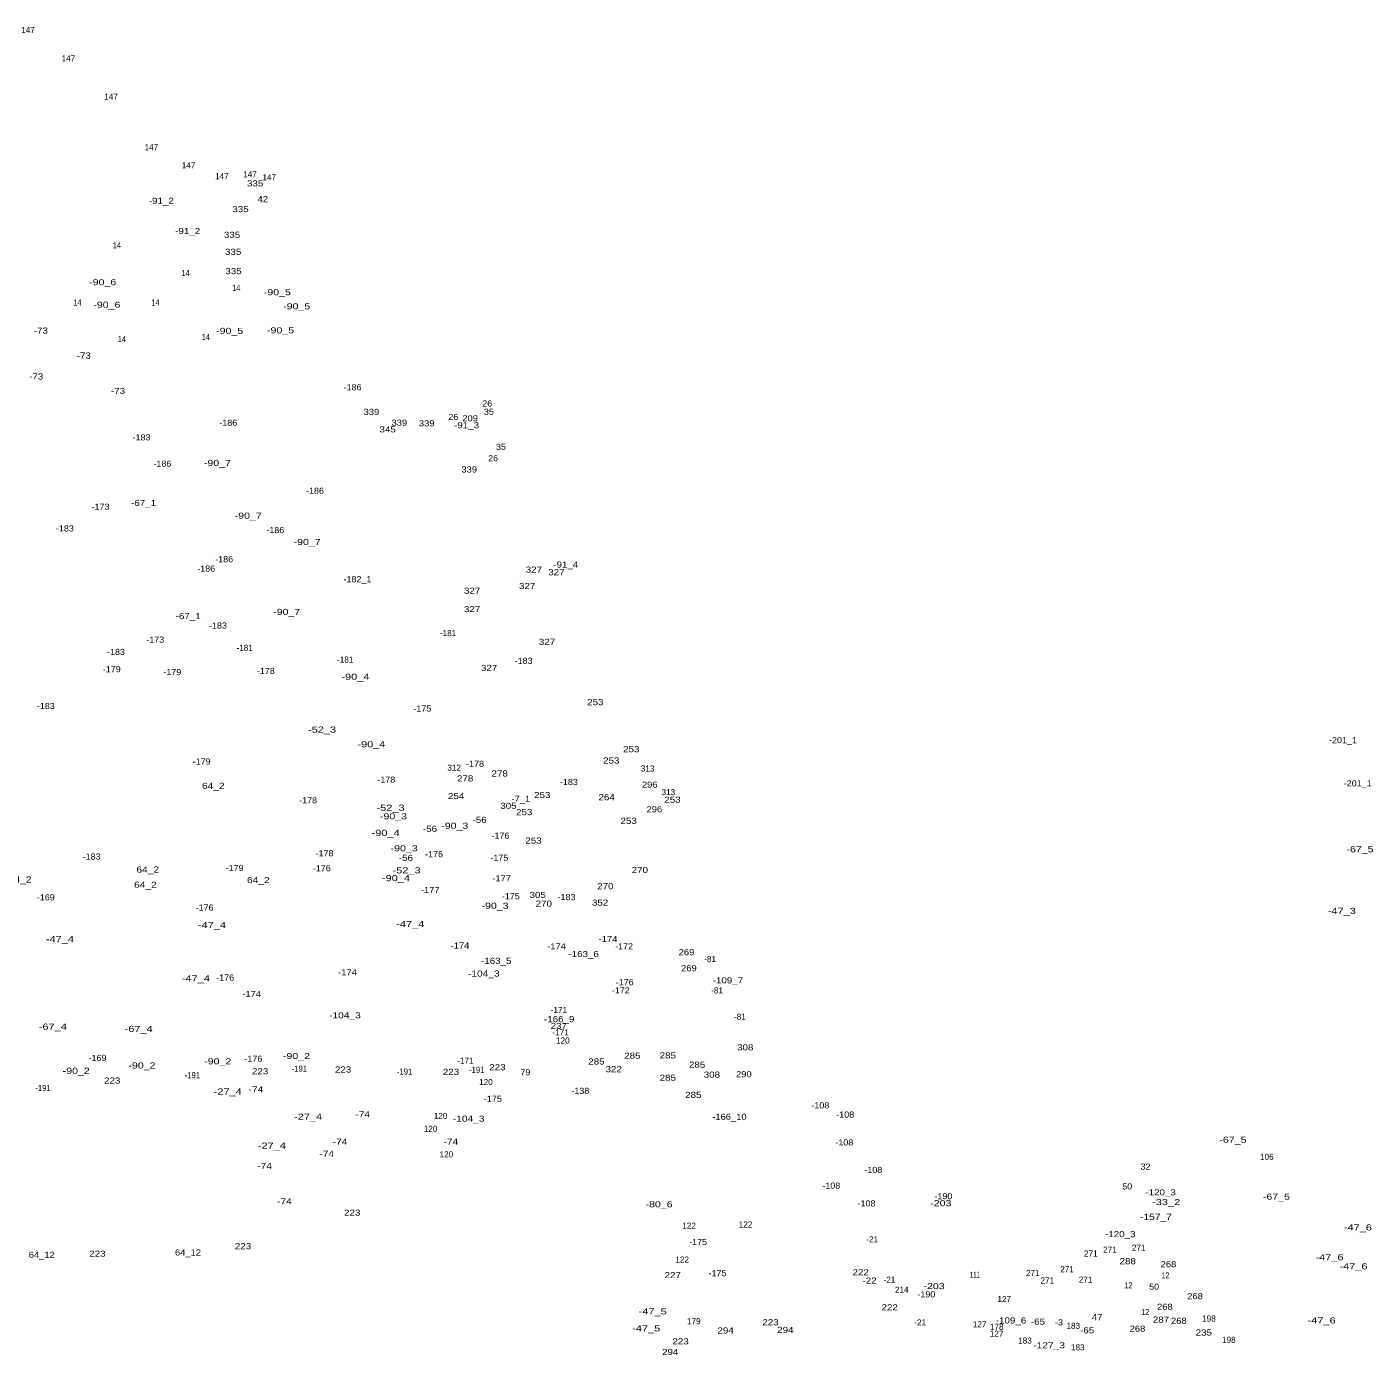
# Model space of a CAD drawing. Extents: x -662996 to -659766, y -998554 to -993949.
# Drawn here: x -661835 to -660951, y -995097 to -994225 of the extents above; entities that cross this region are included whole.
import ezdxf
from ezdxf.enums import TextEntityAlignment as Align

# ---------------------------------------------------------------- set-up
doc = ezdxf.new("R2010")
doc.units = 0
doc.header["$LTSCALE"] = 1.6
doc.layers.add('24', color=7, linetype='Continuous')

msp = doc.modelspace()

# ---------------------------------------------------------------- texts
at = {"layer": '24'}
for s, p in [('147', (-661833.88, -994229.49)), ('147', (-661807.38, -994248.12)), ('147', (-661779.35, -994273.28)), ('147', (-661752.92, -994306.42)), ('147', (-661728.53, -994318.34)), ('147', (-661706.65, -994325.44)), ('147', (-661688.22, -994324.28)), ('147', (-661675.55, -994326.21)), ('-181', (-661558.181, -994625.39)), ('-181', (-661691.691, -994635.04)), ('-181', (-661625.701, -994642.76)), ('312', (-661554.189, -994713.71)), ('313', (-661427.169, -994714.24)), ('313', (-661413.559, -994729.76)), ('-81', (-661386.181, -994839.38)), ('-81', (-661381.581, -994859.93)), ('-171', (-661485.45, -994872.78)), ('-81', (-661366.601, -994877.22)), ('-171', (-661484.29, -994887.45)), ('120', (-661482.85, -994892.79)), ('-171', (-661546.8, -994905.98)), ('120', (-661533.35, -994920.05)), ('120', (-661563.11, -994942.33)), ('120', (-661569.64, -994950.78)), ('120', (-661559.27, -994967.49)), ('106', (-661020.74, -994969.17)), ('122', (-661399.98, -995014.34)), ('122', (-661362.919, -995013.58)), ('-21', (-661279.801, -995023.32)), ('271', (-661104.851, -995028.81)), ('122', (-661404.49, -995036.62)), ('271', (-661136.27, -995032.62)), ('271', (-661123.701, -995030.14)), ('271', (-661174.351, -995045.38)), ('271', (-661151.88, -995042.9)), ('-21', (-661268.471, -995049.83)), ('214', (-661260.38, -995056.43)), ('271', (-661164.831, -995050.33)), ('271', (-661139.691, -995049.76)), ('127', (-661193.111, -995062.55)), ('179', (-661396.86, -995077.01)), ('-21', (-661248.311, -995077.87)), ('127', (-661209.24, -995079.07)), ('178', (-661198.01, -995080.73)), ('183', (-661147.79, -995080.06)), ('198', (-661058.711, -995075.3)), ('127', (-661198.101, -995085.21)), ('183', (-661179.47, -995089.76)), ('198', (-661045.65, -995089.32)), ('183', (-661144.819, -995094.18))]:
    msp.add_text(s, height=4, dxfattribs=at).set_placement(p, align=Align.CENTER)
for s, width, p in [('335', 1.2, (-661684.809, -994330.17)), ('42', 1.15, (-661679.799, -994340.55)), ('-91_2', 1.2, (-661746.39, -994341.6)), ('335', 1.2, (-661694.419, -994347.07)), ('-91_2', 1.2, (-661729.101, -994361.43)), ('335', 1.2, (-661699.98, -994363.98)), ('14', 0.85, (-661775.559, -994370.91)), ('335', 1.2, (-661699.22, -994375.12)), ('14', 0.85, (-661730.439, -994388.97)), ('335', 1.2, (-661699.02, -994387.79)), ('-90_6', 1.3, (-661784.88, -994395.05)), ('14', 0.85, (-661697.22, -994398.76)), ('-90_5', 1.3, (-661670.26, -994401.64)), ('14', 0.85, (-661801.48, -994408.36)), ('-90_6', 1.3, (-661782.16, -994409.83)), ('14', 0.85, (-661750.22, -994408.36)), ('-90_5', 1.3, (-661657.54, -994410.87)), ('-73', 1.2, (-661825.471, -994426.81)), ('-90_5', 1.3, (-661701.55, -994427.01)), ('-90_5', 1.3, (-661668.13, -994426.62)), ('14', 0.85, (-661772.299, -994432.37)), ('14', 0.85, (-661717.189, -994431.03)), ('-73', 1.2, (-661797.291, -994443.19)), ('-73', 1.2, (-661828.51, -994456.9)), ('-186', 1.1, (-661620.84, -994464.04)), ('-73', 1.2, (-661774.821, -994466.43)), ('339', 1.15, (-661608.48, -994480.17)), ('26', 1.1, (-661532.47, -994474.67)), ('35', 1.1, (-661531.4, -994480.04)), ('-186', 1.1, (-661702.45, -994487.32)), ('339', 1.15, (-661590.15, -994487.28)), ('339', 1.15, (-661572.19, -994487.66)), ('26', 1.1, (-661554.74, -994483.5)), ('-91_3', 1.2, (-661546.03, -994488.93)), ('209', 1.15, (-661543.691, -994484.36)), ('-183', 1.1, (-661759.4, -994496.91)), ('345', 1.2, (-661597.819, -994491.66)), ('35', 1.1, (-661523.429, -994503.09)), ('-186', 1.1, (-661745.67, -994514.15)), ('-90_7', 1.3, (-661709.57, -994513.68)), ('26', 1.1, (-661528.63, -994510.58)), ('339', 1.15, (-661544.28, -994517.98)), ('-186', 1.1, (-661645.54, -994531.91)), ('-173', 1.1, (-661786.28, -994542.42)), ('-67_1', 1.2, (-661758.06, -994539.95)), ('-90_7', 1.3, (-661689.36, -994548.28)), ('-183', 1.1, (-661809.721, -994556.67)), ('-186', 1.1, (-661671.58, -994557.77)), ('-90_7', 1.3, (-661650.68, -994565.58)), ('-186', 1.1, (-661705.15, -994576.88)), ('-186', 1.1, (-661716.92, -994583.05)), ('327', 1.2, (-661501.86, -994583.71)), ('327', 1.2, (-661487.07, -994585.43)), ('-91_4', 1.2, (-661480.9, -994580.4)), ('-182_1', 1.1, (-661617.66, -994589.96)), ('327', 1.2, (-661506.27, -994594.46)), ('327', 1.2, (-661542.37, -994597.53)), ('-67_1', 1.2, (-661728.74, -994614.24)), ('-90_7', 1.3, (-661664.09, -994611.47)), ('327', 1.2, (-661542.37, -994609.63)), ('-183', 1.1, (-661709.24, -994620.43)), ('-173', 1.1, (-661750.39, -994629.66)), ('327', 1.2, (-661493.22, -994631.15)), ('-183', 1.1, (-661776.15, -994637.73)), ('-179', 1.1, (-661778.919, -994649.06)), ('327', 1.2, (-661531.23, -994648.24)), ('-183', 1.1, (-661508.591, -994643.6)), ('-179', 1.1, (-661739.179, -994650.99)), ('-178', 1.1, (-661677.83, -994650.22)), ('-90_4', 1.35, (-661618.98, -994654.02)), ('-183', 1.1, (-661822.221, -994673.24)), ('-175', 1.1, (-661575.06, -994674.88)), ('253', 1.2, (-661461.52, -994670.71)), ('-52_3', 1.35, (-661640.88, -994688.72)), ('-90_4', 1.35, (-661608.49, -994698.35)), ('253', 1.2, (-661437.91, -994701.57)), ('-201_1', 1.1, (-660970.73, -994695.64)), ('-179', 1.1, (-661719.89, -994709.66)), ('-178', 1.1, (-661540.46, -994711.21)), ('253', 1.2, (-661451.049, -994709)), ('278', 1.2, (-661546.94, -994720.76)), ('278', 1.2, (-661524.28, -994717.52)), ('64_2', 1.25, (-661712.299, -994725.66)), ('-178', 1.1, (-661598.72, -994721.63)), ('-183', 1.1, (-661478.88, -994723.11)), ('296', 1.15, (-661425.81, -994724.86)), ('-201_1', 1.1, (-660961.08, -994724.01)), ('-178', 1.1, (-661650.04, -994735.14)), ('254', 1.2, (-661552.89, -994732.36)), ('-7_1', 1.15, (-661510.42, -994734.14)), ('253', 1.2, (-661496.36, -994731.66)), ('264', 1.2, (-661454.09, -994733.1)), ('253', 1.2, (-661410.87, -994734.71)), ('-52_3', 1.35, (-661595.949, -994740)), ('-90_3', 1.3, (-661593.99, -994745.64)), ('305', 1.2, (-661518.54, -994738.76)), ('253', 1.2, (-661508.169, -994742.9)), ('296', 1.15, (-661422.76, -994741.05)), ('-56', 1.2, (-661570.02, -994753.86)), ('-90_3', 1.3, (-661553.76, -994751.86)), ('-56', 1.2, (-661537.46, -994747.96)), ('253', 1.2, (-661439.62, -994748.62)), ('-90_4', 1.35, (-661599.16, -994756.48)), ('-176', 1.1, (-661523.77, -994758.32)), ('253', 1.2, (-661502.079, -994761.57)), ('-183', 1.1, (-661792.13, -994772.06)), ('-178', 1.1, (-661639.24, -994769.88)), ('-90_3', 1.3, (-661586.99, -994766.63)), ('-56', 1.2, (-661585.83, -994772.91)), ('-176', 1.1, (-661567.37, -994770.48)), ('-175', 1.1, (-661524.51, -994772.81)), ('-67_5', 1.3, (-660959.581, -994767.24)), ('64_2', 1.25, (-661755.309, -994780.59)), ('-179', 1.1, (-661698.28, -994779.53)), ('-176', 1.1, (-661641.069, -994779.74)), ('-52_3', 1.35, (-661585.39, -994781.11)), ('270', 1.2, (-661432.28, -994780.86)), ('64_2', 1.25, (-661839.02, -994787.12)), ('64_2', 1.25, (-661756.84, -994790.58)), ('64_2', 1.25, (-661682.73, -994787.51)), ('-90_4', 1.35, (-661592.36, -994786.22)), ('-177', 1.15, (-661523, -994786.3)), ('-169', 1.1, (-661822.23, -994798.84)), ('-177', 1.15, (-661569.88, -994794.02)), ('-175', 1.1, (-661516.99, -994798.09)), ('305', 1.2, (-661499.309, -994797.24)), ('-183', 1.1, (-661480.421, -994798.68)), ('270', 1.2, (-661454.94, -994791.52)), ('-176', 1.1, (-661717.99, -994805.52)), ('-90_3', 1.3, (-661527.33, -994804.35)), ('270', 1.2, (-661495.31, -994802.95)), ('352', 1.2, (-661458.38, -994802.32)), ('-47_3', 1.35, (-660971.52, -994807.72)), ('-47_4', 1.35, (-661713.15, -994817.06)), ('-47_4', 1.35, (-661582.97, -994816.29)), ('-47_4', 1.35, (-661812.99, -994826.28)), ('-174', 1.15, (-661453.201, -994826.22)), ('-174', 1.15, (-661550.321, -994830.47)), ('-174', 1.15, (-661486.961, -994831.05)), ('-172', 1.1, (-661442.62, -994830.95)), ('269', 1.15, (-661401.69, -994834.86)), ('-163_5', 1.2, (-661526.571, -994840.51)), ('-163_6', 1.2, (-661469.19, -994836.06)), ('-47_4', 1.35, (-661723.75, -994852.02)), ('-176', 1.1, (-661704.49, -994851.46)), ('-174', 1.15, (-661624.211, -994848.03)), ('-104_3', 1.25, (-661534.709, -994848.85)), ('269', 1.15, (-661400.08, -994845.33)), ('-109_7', 1.2, (-661374.47, -994853.31)), ('-172', 1.1, (-661444.74, -994859.9)), ('-176', 1.1, (-661442.25, -994854.54)), ('-174', 1.15, (-661687.111, -994862.31)), ('-104_3', 1.25, (-661625.86, -994876.26)), ('-166_9', 1.2, (-661485.23, -994878.79)), ('-67_4', 1.35, (-661817.611, -994883.67)), ('-67_4', 1.35, (-661761.25, -994885.19)), ('237', 1.2, (-661485.49, -994883.24)), ('308', 1.2, (-661363.1, -994897.3)), ('-169', 1.1, (-661788.27, -994904.22)), ('-176', 1.1, (-661685.97, -994904.73)), ('-90_2', 1.3, (-661657.67, -994902.98)), ('285', 1.2, (-661437.169, -994902.76)), ('285', 1.2, (-661413.939, -994902.57)), ('-90_2', 1.3, (-661802.25, -994912.7)), ('-90_2', 1.3, (-661759.11, -994909.2)), ('-90_2', 1.3, (-661709.36, -994906.48)), ('223', 1.2, (-661681.53, -994912.99)), ('-191', 0.95, (-661655.79, -994911.29)), ('223', 1.2, (-661627.069, -994911.85)), ('-191', 0.95, (-661586.72, -994913.22)), ('223', 1.2, (-661556.24, -994913.37)), ('-191', 0.95, (-661539.37, -994912.06)), ('223', 1.2, (-661525.78, -994910.32)), ('79', 1.1, (-661507.41, -994913.63)), ('285', 1.2, (-661460.78, -994906.57)), ('322', 1.2, (-661449.429, -994911.61)), ('285', 1.2, (-661394.709, -994908.67)), ('308', 1.2, (-661384.99, -994915.2)), ('290', 1.15, (-661364, -994914.92)), ('-191', 0.95, (-661824.03, -994924.03)), ('223', 1.2, (-661778.64, -994919.09)), ('-191', 0.95, (-661726.02, -994915.54)), ('285', 1.2, (-661413.939, -994917.24)), ('-27_4', 1.35, (-661702.819, -994926.28)), ('-74', 1.25, (-661684.301, -994924.9)), ('-175', 1.1, (-661528.77, -994931.03)), ('-138', 1.1, (-661471.361, -994925.79)), ('285', 1.2, (-661397.179, -994928.48)), ('-74', 1.25, (-661614.231, -994941.29)), ('-108', 1.1, (-661313.811, -994935.38)), ('-108', 1.1, (-661297.481, -994941.41)), ('-27_4', 1.35, (-661650.02, -994942.8)), ('-104_3', 1.25, (-661544.64, -994944.11)), ('-166_10', 1.15, (-661373.5, -994942.89)), ('-74', 1.25, (-661629.081, -994959.19)), ('-74', 1.25, (-661556.341, -994959.19)), ('-67_5', 1.3, (-661042.981, -994957.95)), ('-27_4', 1.35, (-661673.829, -994961.82)), ('-74', 1.25, (-661637.841, -994967.19)), ('-108', 1.1, (-661298.071, -994959.68)), ('-74', 1.25, (-661678.591, -994975.19)), ('32', 1.1, (-661100.39, -994975.59)), ('-108', 1.1, (-661279.02, -994977.76)), ('-108', 1.1, (-661306.62, -994988.07)), ('50', 1.1, (-661112.34, -994988.6)), ('-120_3', 1.2, (-661090.47, -994992.48)), ('-74', 1.25, (-661665.64, -994998.43)), ('-80_6', 1.3, (-661419.69, -995000.33)), ('-108', 1.1, (-661283.49, -994999.73)), ('-203', 1.3, (-661234.71, -994999.59)), ('-190', 1.1, (-661233.03, -994995)), ('-33_2', 1.35, (-661086.79, -994998.86)), ('-67_5', 1.3, (-661014.421, -994995.28)), ('223', 1.2, (-661621.09, -995005.8)), ('-157_7', 1.25, (-661093.54, -995008.58)), ('-120_3', 1.2, (-661116.929, -995019.9)), ('-47_6', 1.35, (-660960.971, -995015.51)), ('223', 1.2, (-661692.76, -995027.78)), ('-175', 1.1, (-661394.06, -995025.07)), ('64_12', 1.15, (-661824.89, -995033.47)), ('223', 1.2, (-661788.34, -995032.73)), ('64_12', 1.15, (-661728.88, -995031.94)), ('288', 1.2, (-661112.04, -995037.67)), ('-47_6', 1.35, (-660979.591, -995035.1)), ('227', 1.2, (-661410.65, -995046.81)), ('-175', 1.1, (-661381.33, -995045.52)), ('222', 1.2, (-661287.319, -995044.95)), ('111', 0.6, (-661212.31, -995046.56)), ('268', 1.15, (-661085.26, -995039.66)), ('12', 0.8, (-661087.28, -995047)), ('-47_6', 1.35, (-660963.851, -995041.06)), ('-22', 1.2, (-661281.53, -995050.4)), ('-203', 1.3, (-661239.15, -995054.01)), ('12', 0.8, (-661111.66, -995053.53)), ('50', 1.1, (-661094.699, -995054.42)), ('-190', 1.1, (-661244.22, -995059.46)), ('268', 1.15, (-661067.84, -995060.61)), ('-47_5', 1.35, (-661423.87, -995070.62)), ('222', 1.2, (-661268.28, -995067.97)), ('12', 0.8, (-661100.53, -995071.01)), ('268', 1.15, (-661087.64, -995067.57)), ('-47_5', 1.35, (-661428.1, -995081.76)), ('223', 1.2, (-661346.52, -995077.72)), ('294', 1.2, (-661336.76, -995082.76)), ('-109_6', 1.2, (-661188.65, -995076.57)), ('-65', 1.2, (-661170.98, -995077.32)), ('-3', 1.1, (-661157.14, -995077.81)), ('-65', 1.2, (-661138.66, -995083.05)), ('47', 1.15, (-661132.11, -995074.39)), ('268', 1.15, (-661105.63, -995081.95)), ('287', 1.2, (-661090.2, -995076)), ('268', 1.15, (-661078.5, -995076.8)), ('-47_6', 1.35, (-660984.78, -995076.54)), ('223', 1.2, (-661405.549, -995090.29)), ('294', 1.2, (-661375.98, -995083.14)), ('235', 1.2, (-661062.09, -995084.48)), ('294', 1.2, (-661412.35, -995097.24)), ('-127_3', 1.25, (-661163.65, -995092.86))]:
    msp.add_text(s, height=4, dxfattribs=dict(at, width=width)).set_placement(p, align=Align.CENTER)

doc.saveas('drawing.dxf')
